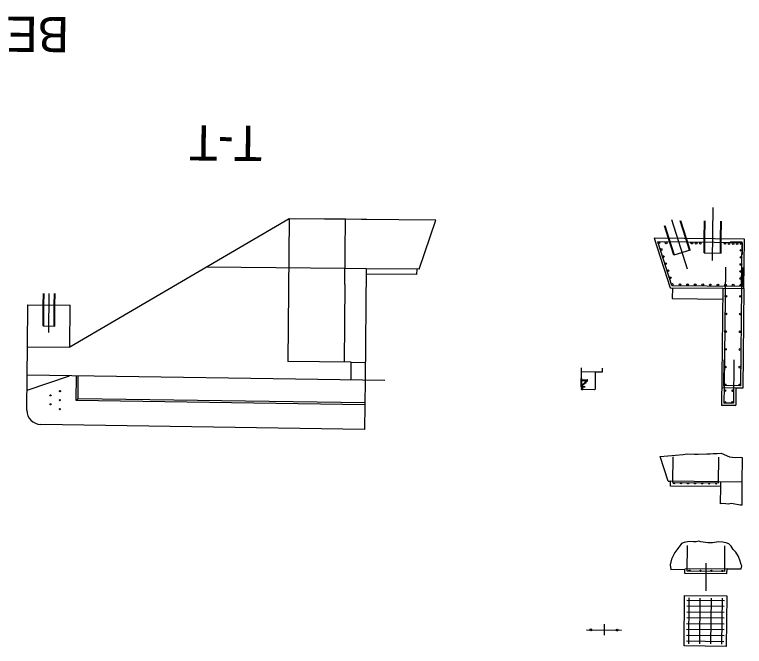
# Model space of a CAD drawing. Extents: x 631918 to 632319, y 373181 to 373282.
# Drawn here: x 632168.3 to 632220.2, y 373206.1 to 373251 of the extents above; entities that cross this region are included whole.
import ezdxf

# ---------------------------------------------------------------- set-up
doc = ezdxf.new("R2010")
doc.units = 0
for name, color, linetype in [('B_Boring', 7, 'Continuous'), ('B_Boring Annot', 7, 'Continuous'), ('BD-EXIST-COSS', 7, 'Continuous'), ('BD-LEGEND', 7, 'Continuous'), ('BD-PROP-COSS', 7, 'Continuous'), ('BD-PROP-OSB', 7, 'Continuous'), ('BD-REMOVE', 7, 'Continuous'), ('R_Anno_Text', 7, 'Continuous'), ('R_Border_Scale', 7, 'Continuous'), ('R_Proposed Const Limits Cut', 7, 'Continuous'), ('R_Proposed Const Limits Fill', 7, 'Continuous'), ('R_Road Edge of Shoulder', 7, 'Continuous'), ('R_Road Edge of Travel', 7, 'Continuous'), ('R_Shade Removal', 7, 'Continuous'), ('R_Wall', 7, 'Continuous')]:
    doc.layers.add(name, color=color, linetype=linetype)

msp = doc.modelspace()

# ---------------------------------------------------------------- linework, layer by layer
at = {"layer": 'B_Boring'}
for p, q in [((632187.827, 373236.507), (632187.726, 373226.351)), ((632191.78, 373231.833), (632191.725, 373226.311)), ((632192.225, 373226.306), (632187.726, 373226.351)), ((632192.213, 373225.056), (632192.225, 373226.306)), ((632169.205, 373224.316), (632172.215, 373225.355))]:
    msp.add_line(p, q, dxfattribs=at)
at = {"layer": 'B_Boring Annot'}
msp.add_line((632208.934, 373207.299), (632211.434, 373207.274), dxfattribs=at)
at = {"layer": 'BD-EXIST-COSS'}
msp.add_line((632208.548, 373224.537), (632208.553, 373225.12), dxfattribs=at)
at = {"layer": 'BD-LEGEND'}
for p, q in [((632214.731, 373217.849), (632214.166, 373219.605)), ((632219.999, 373219.547), (632219.981, 373217.797)), ((632214.731, 373217.849), (632214.898, 373217.848)), ((632219.981, 373217.797), (632219.965, 373216.163)), ((632218.466, 373216.251), (632218.478, 373217.479))]:
    msp.add_line(p, q, dxfattribs=at)
at = {"layer": 'BD-PROP-COSS'}
for p, q in [((632214.99, 373231.769), (632213.993, 373234.862)), ((632220.025, 373234.802), (632213.993, 373234.862)), ((632219.984, 373234.844), (632219.151, 373234.852)), ((632219.953, 373231.719), (632219.984, 373234.844)), ((632220.017, 373233.969), (632220.025, 373234.802)), ((632218.799, 373233.057), (632218.716, 373224.648)), ((632220.018, 373233.045), (632220.005, 373231.719)), ((632214.99, 373231.769), (632219.953, 373231.719)), ((632219.952, 373231.648), (632219.882, 373224.636)), ((632220.005, 373231.719), (632219.952, 373231.648)), ((632218.69, 373226.482), (632218.672, 373224.648)), ((632219.401, 373226.475), (632219.37, 373223.391)), ((632218.672, 373224.648), (632218.715, 373224.595)), ((632218.715, 373224.595), (632218.703, 373223.398)), ((632219.882, 373224.636), (632218.716, 373224.648)), ((632219.37, 373223.391), (632218.703, 373223.398)), ((632215.064, 373217.763), (632215.082, 373219.596)), ((632218.314, 373217.731), (632218.332, 373219.564)), ((632215.064, 373217.763), (632218.314, 373217.731)), ((632216.085, 373211.46), (632216.103, 373213.294)), ((632218.751, 373211.434), (632218.769, 373213.267)), ((632218.751, 373211.434), (632216.085, 373211.46)), ((632216.2, 373206.31), (632216.232, 373209.56)), ((632216.978, 373206.302), (632217.01, 373209.552)), ((632217.788, 373209.544), (632217.756, 373206.294)), ((632218.566, 373209.536), (632218.533, 373206.287)), ((632218.726, 373208.951), (632216.06, 373208.978)), ((632216.064, 373209.395), (632218.731, 373209.368)), ((632218.722, 373208.535), (632216.056, 373208.561)), ((632218.718, 373208.118), (632216.052, 373208.145)), ((632218.714, 373207.701), (632216.048, 373207.728)), ((632218.71, 373207.285), (632216.043, 373207.311)), ((632218.702, 373206.452), (632216.035, 373206.478)), ((632218.706, 373206.868), (632216.039, 373206.895))]:
    msp.add_line(p, q, dxfattribs=at)
for centre, radius in [((632214.08, 373234.799), 0.0625), ((632214.235, 373234.318), 0.0625), ((632214.587, 373234.794), 0.0625), ((632216.421, 373234.775), 0.0625), ((632216.421, 373234.775), 0.0625), ((632216.723, 373234.772), 0.0625), ((632217.025, 373234.769), 0.0625), ((632218.775, 373234.752), 0.0625), ((632218.775, 373234.752), 0.0625), ((632219.061, 373234.749), 0.0625), ((632219.348, 373234.746), 0.0625), ((632219.634, 373234.744), 0.0625), ((632219.92, 373234.741), 0.0625), ((632214.396, 373233.816), 0.0625), ((632219.916, 373234.262), 0.0625), ((632214.558, 373233.315), 0.0625), ((632219.911, 373233.762), 0.0625), ((632214.72, 373232.813), 0.0625), ((632219.901, 373232.762), 0.0625), ((632219.906, 373233.262), 0.0625), ((632214.881, 373232.311), 0.0625), ((632219.896, 373232.262), 0.0625), ((632215.036, 373231.831), 0.0625), ((632215.036, 373231.831), 0.0625), ((632215.575, 373231.825), 0.0625), ((632216.115, 373231.82), 0.0625), ((632216.654, 373231.815), 0.0625), ((632217.194, 373231.809), 0.0625), ((632217.733, 373231.804), 0.0625), ((632218.273, 373231.799), 0.0625), ((632218.812, 373231.793), 0.0625), ((632219.352, 373231.788), 0.0625), ((632219.891, 373231.782), 0.0625), ((632218.842, 373231.001), 0.0625), ((632218.842, 373231.001), 0.0625), ((632219.883, 373230.991), 0.0625), ((632218.829, 373229.743), 0.0625), ((632219.871, 373229.733), 0.0625), ((632218.817, 373228.485), 0.0625), ((632219.858, 373228.474), 0.0625), ((632218.804, 373227.226), 0.0625), ((632219.846, 373227.216), 0.0625), ((632218.791, 373225.968), 0.0625), ((632219.833, 373225.958), 0.0625), ((632218.779, 373224.71), 0.0625), ((632219.821, 373224.7), 0.0625), ((632218.775, 373224.293), 0.0625), ((632219.316, 373224.288), 0.0625), ((632218.767, 373223.46), 0.0625), ((632219.308, 373223.455), 0.0625), ((632215.147, 373217.72), 0.0417), ((632215.647, 373217.715), 0.0417), ((632216.147, 373217.71), 0.0417), ((632216.647, 373217.705), 0.0417), ((632217.147, 373217.7), 0.0417), ((632217.647, 373217.695), 0.0417), ((632218.147, 373217.691), 0.0417), ((632216.252, 373211.5), 0.0417), ((632217.029, 373211.493), 0.0417), ((632217.807, 373211.485), 0.0417), ((632218.585, 373211.477), 0.0417)]:
    msp.add_circle(centre, radius, dxfattribs=at)
at = {"layer": 'BD-PROP-OSB'}
for p, q in [((632208.553, 373225.131), (632208.586, 373225.097)), ((632208.553, 373225.086), (632208.586, 373225.053)), ((632208.57, 373225.161), (632208.587, 373225.145)), ((632208.548, 373224.599), (632208.61, 373224.536)), ((632208.548, 373224.555), (632208.565, 373224.536)), ((632208.549, 373224.643), (632208.654, 373224.536)), ((632208.55, 373224.82), (632208.583, 373224.787)), ((632208.55, 373224.776), (632208.583, 373224.742)), ((632208.551, 373224.909), (632208.584, 373224.875)), ((632208.551, 373224.865), (632208.584, 373224.831)), ((632208.552, 373224.998), (632208.585, 373224.964)), ((632208.552, 373224.953), (632208.585, 373224.92)), ((632208.553, 373225.042), (632208.586, 373225.008)), ((632208.633, 373224.602), (632208.698, 373224.535)), ((632208.685, 373224.593), (632208.724, 373224.553)), ((632208.731, 373224.535), (632208.732, 373224.585)), ((632208.738, 373224.535), (632208.739, 373224.584)), ((632208.745, 373224.535), (632208.746, 373224.583)), ((632208.752, 373224.535), (632208.753, 373224.582)), ((632208.759, 373224.535), (632208.759, 373224.581)), ((632208.766, 373224.534), (632208.766, 373224.58)), ((632208.773, 373224.534), (632208.773, 373224.578)), ((632208.78, 373224.534), (632208.78, 373224.577)), ((632208.787, 373224.534), (632208.787, 373224.576)), ((632208.794, 373224.534), (632208.794, 373224.575)), ((632208.801, 373224.534), (632208.801, 373224.573)), ((632208.808, 373224.534), (632208.808, 373224.571)), ((632208.815, 373224.534), (632208.815, 373224.567)), ((632208.822, 373224.534), (632208.822, 373224.56)), ((632208.828, 373224.534), (632208.829, 373224.548))]:
    msp.add_line(p, q, dxfattribs=at)
for points in [[(632208.617, 373224.515), (632208.596, 373224.536)], [(632208.682, 373224.479), (632208.627, 373224.536)], [(632208.683, 373224.509), (632208.657, 373224.536)], [(632208.61, 373224.369), (632208.567, 373224.413)], [(632208.64, 373224.369), (632208.577, 373224.434)], [(632208.599, 373224.503), (632208.584, 373224.518)], [(632208.671, 373224.369), (632208.627, 373224.414)], [(632208.681, 373224.388), (632208.64, 373224.431)], [(632208.682, 373224.419), (632208.648, 373224.453)], [(632208.682, 373224.449), (632208.652, 373224.48)]]:
    msp.add_lwpolyline(points, dxfattribs=at)
at = {"layer": 'R_Anno_Text'}
for centre in [(632209.246, 373207.296), (632211.121, 373207.277)]:
    msp.add_circle(centre, 0.0625, dxfattribs=at)
at = {"layer": 'R_Border_Scale'}
for p, q in [((632191.78, 373231.833), (632191.826, 373236.467)), ((632191.792, 373232.967), (632181.954, 373233.065)), ((632193.292, 373232.952), (632191.792, 373232.967)), ((632218.618, 373231.566), (632220.118, 373231.551)), ((632192.225, 373226.306), (632193.225, 373226.296)), ((632209.558, 373225.61), (632208.558, 373225.62)), ((632194.613, 373225.02), (632169.215, 373225.4)), ((632219.547, 373224.473), (632218.548, 373224.483)), ((632219.981, 373217.797), (632214.898, 373217.848)), ((632218.478, 373217.479), (632218.481, 373217.812)), ((632218.92, 373211.629), (632215.919, 373211.599))]:
    msp.add_line(p, q, dxfattribs=at)
at = {"layer": 'R_Proposed Const Limits Cut'}
for p, q in [((632208.548, 373224.537), (632208.554, 373225.162)), ((632208.554, 373225.162), (632208.587, 373225.161)), ((632208.587, 373225.161), (632208.582, 373224.656)), ((632208.586, 373225.062), (632208.975, 373225.058)), ((632208.974, 373224.975), (632208.975, 373225.09)), ((632208.975, 373225.09), (632209.014, 373225.089)), ((632209.013, 373224.975), (632209.014, 373225.089)), ((632208.724, 373224.535), (632208.548, 373224.537)), ((632208.583, 373224.647), (632208.843, 373224.902)), ((632208.584, 373224.536), (632208.584, 373224.503)), ((632208.586, 373225.01), (632208.974, 373225.006)), ((632208.615, 373224.606), (632208.879, 373224.865)), ((632208.626, 373224.604), (632208.725, 373224.587)), ((632208.681, 373224.369), (632208.683, 373224.535)), ((632208.821, 373224.925), (632208.849, 373224.952)), ((632208.901, 373224.843), (632208.821, 373224.925)), ((632208.929, 373224.87), (632208.849, 373224.952)), ((632208.901, 373224.843), (632208.929, 373224.87)), ((632208.974, 373224.975), (632209.013, 373224.975)), ((632208.589, 373224.434), (632208.567, 373224.434)), ((632208.567, 373224.434), (632208.567, 373224.396)), ((632208.567, 373224.396), (632208.583, 373224.37)), ((632208.583, 373224.37), (632208.681, 373224.369)), ((632208.584, 373224.503), (632208.606, 373224.503))]:
    msp.add_line(p, q, dxfattribs=at)
msp.add_arc((632208.635, 373224.656), 0.0529, 179.4304, 259.9304, dxfattribs=at)
msp.add_ellipse((632208.62, 373224.463), major_axis=(0.0134, 0.0564), ratio=0.508295, start_param=2.236026, end_param=7.19143, dxfattribs=at)
at = {"layer": 'R_Proposed Const Limits Fill'}
for p, q in [((632217.424, 373212.034), (632217.404, 373210.054)), ((632210.188, 373207.69), (632210.18, 373206.912))]:
    msp.add_line(p, q, dxfattribs=at)
at = {"layer": 'R_Road Edge of Shoulder'}
for p, q in [((632208.549, 373224.672), (632208.582, 373224.672)), ((632208.55, 373224.735), (632208.583, 373224.734)), ((632208.724, 373224.535), (632208.725, 373224.587)), ((632208.831, 373224.534), (632208.724, 373224.535)), ((632208.725, 373224.587), (632208.797, 373224.574))]:
    msp.add_line(p, q, dxfattribs=at)
msp.add_arc((632208.79, 373224.534), 0.0407, 359.4304, 79.9304, dxfattribs=at)
at = {"layer": 'R_Road Edge of Travel'}
for p, q in [((632214.762, 373235.104), (632214.475, 373235.995)), ((632214.813, 373235.104), (632214.521, 373236.01)), ((632215.993, 373235.092), (632215.586, 373236.353)), ((632216.044, 373235.092), (632215.633, 373236.368)), ((632217.294, 373235.079), (632217.307, 373236.352)), ((632217.343, 373235.079), (632217.356, 373236.351)), ((632218.462, 373235.068), (632218.475, 373236.34)), ((632218.511, 373235.067), (632218.524, 373236.34)), ((632215.147, 373233.908), (632214.762, 373235.104)), ((632215.194, 373233.923), (632214.813, 373235.104)), ((632216.259, 373234.266), (632215.993, 373235.092)), ((632216.305, 373234.281), (632216.044, 373235.092)), ((632217.285, 373234.079), (632217.294, 373235.079)), ((632217.333, 373234.079), (632217.343, 373235.079)), ((632218.452, 373234.068), (632218.462, 373235.068)), ((632218.501, 373234.067), (632218.511, 373235.067)), ((632216.305, 373234.281), (632215.147, 373233.908)), ((632217.285, 373234.079), (632218.501, 373234.067)), ((632170.348, 373230.389), (632170.356, 373231.192)), ((632170.395, 373230.388), (632170.403, 373231.192)), ((632171.135, 373230.381), (632171.143, 373231.184)), ((632171.182, 373230.38), (632171.19, 373231.184)), ((632170.333, 373228.889), (632170.348, 373230.389)), ((632170.38, 373228.888), (632170.395, 373230.388)), ((632171.12, 373228.881), (632171.135, 373230.381)), ((632171.167, 373228.88), (632171.182, 373230.38)), ((632170.333, 373228.889), (632171.167, 373228.88))]:
    msp.add_line(p, q, dxfattribs=at)
at = {"layer": 'R_Shade Removal'}
for p, q in [((632187.827, 373236.507), (632172.235, 373227.37)), ((632193.326, 373236.452), (632187.827, 373236.507)), ((632191.826, 373236.467), (632187.827, 373236.507)), ((632198.243, 373236.403), (632190.327, 373236.482)), ((632197.041, 373232.915), (632198.243, 373236.403)), ((632220.153, 373235.051), (632213.736, 373235.115)), ((632213.736, 373235.115), (632214.868, 373231.603)), ((632220.118, 373231.551), (632220.153, 373235.051)), ((632193.292, 373232.952), (632193.213, 373225.041)), ((632197.041, 373232.915), (632193.292, 373232.952)), ((632196.875, 373232.917), (632196.871, 373232.542)), ((632196.871, 373232.542), (632193.288, 373232.577)), ((632214.868, 373231.603), (632218.618, 373231.566)), ((632215.035, 373231.602), (632215.027, 373230.833)), ((632218.618, 373231.566), (632218.535, 373223.233)), ((632220.118, 373231.551), (632220.047, 373224.468)), ((632215.027, 373230.833), (632218.61, 373230.798)), ((632169.235, 373227.4), (632169.265, 373230.399)), ((632169.265, 373230.399), (632172.265, 373230.37)), ((632172.235, 373227.37), (632172.265, 373230.37)), ((632169.215, 373225.4), (632169.235, 373227.4)), ((632169.235, 373227.4), (632172.235, 373227.37)), ((632208.561, 373225.908), (632208.554, 373225.162)), ((632209.558, 373225.61), (632209.546, 373224.402)), ((632210.058, 373225.605), (632209.558, 373225.61)), ((632210.061, 373225.893), (632210.058, 373225.605)), ((632169.19, 373222.895), (632169.215, 373225.4)), ((632172.698, 373223.597), (632172.715, 373225.347)), ((632172.824, 373223.718), (632172.84, 373225.346)), ((632193.213, 373225.041), (632193.178, 373221.541)), ((632209.504, 373224.36), (632208.681, 373224.369)), ((632209.504, 373224.36), (632209.546, 373224.402)), ((632219.547, 373224.473), (632219.535, 373223.265)), ((632220.047, 373224.468), (632219.547, 373224.473)), ((632172.824, 373223.718), (632172.698, 373223.597)), ((632193.196, 373223.291), (632172.698, 373223.597)), ((632193.197, 373223.414), (632172.824, 373223.718)), ((632219.493, 373223.224), (632218.535, 373223.233)), ((632219.493, 373223.224), (632219.535, 373223.265)), ((632193.178, 373221.541), (632170.175, 373221.885)), ((632214.895, 373217.515), (632214.898, 373217.848)), ((632218.478, 373217.479), (632214.895, 373217.515)), ((632214.919, 373211.589), (632215.919, 373211.599)), ((632215.916, 373211.295), (632215.919, 373211.599)), ((632218.916, 373211.266), (632218.92, 373211.629)), ((632218.92, 373211.629), (632219.92, 373211.639)), ((632218.916, 373211.266), (632215.916, 373211.295))]:
    msp.add_line(p, q, dxfattribs=at)
for points in [[(632214.166, 373219.605), (632215.806, 373219.744), (632216.083, 373219.803), (632216.61, 373219.781), (632216.873, 373219.778), (632217.488, 373219.789), (632217.726, 373219.805), (632217.945, 373219.82), (632218.227, 373219.835), (632218.508, 373219.841), (632218.508, 373219.841), (632219.103, 373219.589), (632219.287, 373219.569), (632219.515, 373219.541), (632219.884, 373219.555), (632219.999, 373219.547)], [(632219.965, 373216.163), (632219.851, 373216.16), (632219.354, 373216.241), (632219.209, 373216.267), (632219.023, 373216.234), (632218.837, 373216.241), (632218.526, 373216.264), (632218.466, 373216.251)], [(632219.92, 373211.639), (632219.963, 373211.831), (632219.923, 373211.931), (632219.923, 373211.931), (632219.856, 373212.168), (632219.738, 373212.516), (632219.551, 373212.824), (632219.362, 373213.002), (632219.204, 373213.249), (632219.039, 373213.407), (632218.985, 373213.437), (632218.919, 373213.453), (632218.624, 373213.521), (632218.308, 373213.55), (632217.876, 373213.484), (632217.549, 373213.477), (632217.053, 373213.557), (632216.908, 373213.584), (632216.722, 373213.55), (632216.536, 373213.557), (632216.225, 373213.58), (632215.883, 373213.508), (632215.686, 373213.44), (632215.635, 373213.36), (632215.503, 373213.171), (632215.203, 373212.787), (632214.982, 373212.312), (632214.883, 373211.911), (632214.919, 373211.589)]]:
    msp.add_lwpolyline(points, dxfattribs=at)
msp.add_lwpolyline([(632218.865, 373206.117), (632215.865, 373206.146), (632215.901, 373209.73), (632218.901, 373209.7)], close=True, dxfattribs=at)
for centre in [(632171.537, 373224.25), (632170.868, 373223.956), (632171.531, 373223.615), (632170.861, 373223.32), (632171.525, 373222.979)]:
    msp.add_circle(centre, 0.0417, dxfattribs=at)
msp.add_arc((632170.19, 373222.885), 1, 179.4304, 269.1439, dxfattribs=at)
at = {"layer": 'R_Wall'}
for p, q in [((632217.887, 373233.533), (632217.925, 373237.297)), ((632214.968, 373236.448), (632216.094, 373232.953)), ((632170.745, 373228.425), (632170.773, 373231.188))]:
    msp.add_line(p, q, dxfattribs=at)

# ---------------------------------------------------------------- texts
at = {"layer": 'BD-REMOVE'}
for s, p in [('BENT NO. 1', (632172.191, 373250.83)), ('T-T', (632185.927, 373243.1))]:
    msp.add_text(s, height=2.5, rotation=179.4304, dxfattribs=at).set_placement(p)

doc.saveas('drawing.dxf')
